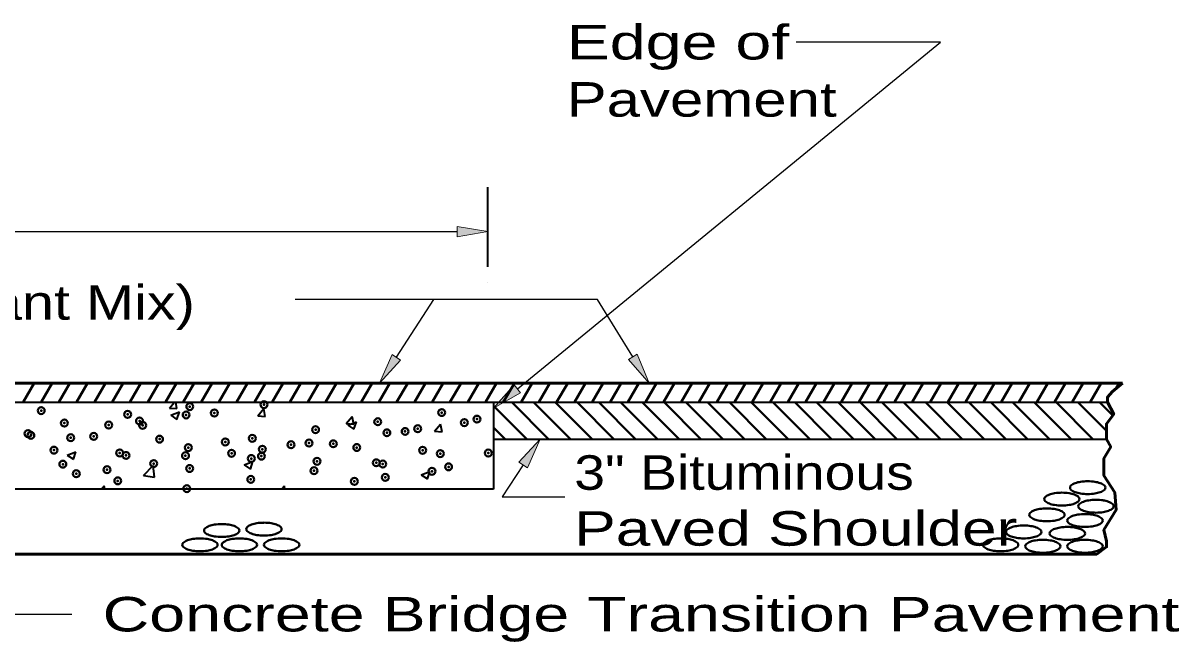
# Model space of a CAD drawing. Extents: x 36.4 to 71.7, y 0.5 to 22.5.
# Drawn here: x 57.119 to 61.81, y 3.21 to 5.719 of the extents above; entities that cross this region are included whole.
import ezdxf

# ---------------------------------------------------------------- set-up
doc = ezdxf.new("R2010")
doc.units = 0
doc.header["$LTSCALE"] = 0.056
doc.header["$PDMODE"] = 32
doc.header["$PDSIZE"] = 0.028
for name, color, linetype, lineweight in [('1', 7, 'Continuous', 40), ('3', 7, 'Continuous', 13), ('6', 7, 'Continuous', 13)]:
    doc.layers.add(name, color=color, linetype=linetype, lineweight=lineweight)

msp = doc.modelspace()

# ---------------------------------------------------------------- hatches: boundary and pattern name
at = {"layer": '1'}
msp.add_hatch(color=256, dxfattribs=at).paths.add_polyline_path([(58.88025, 4.85283), (58.88025, 4.8945), (59.00525, 4.87358), (59.00525, 4.87358)])
at = {"layer": '3'}
for points in [[(58.65083, 4.35233), (58.61592, 4.37517), (58.56508, 4.25908), (58.56508, 4.25908)], [(59.611, 4.37633), (59.57558, 4.35433), (59.65917, 4.25908), (59.65917, 4.25908)], [(59.13783, 4.22), (59.1115, 4.25225), (59.02792, 4.157), (59.02792, 4.157)], [(59.13108, 3.939), (59.16575, 3.916), (59.21733, 4.03183), (59.21733, 4.03183)]]:
    msp.add_hatch(color=256, dxfattribs=at).paths.add_polyline_path(points)

# ---------------------------------------------------------------- linework, layer by layer
at = {"layer": '1', "lineweight": 35}
for p, q in [((59.00525, 4.731), (59.00525, 5.05367)), ((55.79492, 4.1815), (59.02792, 4.1815)), ((57.71308, 4.15808), (57.73275, 4.1815)), ((57.743, 4.1555), (57.73825, 4.1815)), ((59.02792, 4.1815), (59.02792, 3.82925)), ((59.02792, 4.1815), (61.51975, 4.1815)), ((57.71308, 4.15808), (57.743, 4.1555)), ((57.71775, 4.12875), (57.75283, 4.14217)), ((57.71775, 4.12875), (57.74267, 4.11192)), ((57.74267, 4.11192), (57.75283, 4.14217)), ((58.07175, 4.12675), (58.09583, 4.1555)), ((58.10167, 4.12408), (58.09583, 4.15542)), ((58.07175, 4.12675), (58.10167, 4.12408)), ((58.43042, 4.09533), (58.4545, 4.12408)), ((58.43042, 4.09533), (58.46025, 4.09275)), ((58.43633, 4.08867), (58.47133, 4.10208)), ((58.43633, 4.08867), (58.46125, 4.07192)), ((58.46025, 4.09275), (58.4545, 4.12408)), ((58.46125, 4.07192), (58.47133, 4.10208)), ((58.789, 4.064), (58.81308, 4.09275)), ((58.81892, 4.06133), (58.81308, 4.09267)), ((58.789, 4.064), (58.81892, 4.06133)), ((59.02792, 4.03183), (61.5155, 4.03183)), ((57.29767, 3.96742), (57.33267, 3.98092)), ((57.29767, 3.96742), (57.32258, 3.95067)), ((57.32258, 3.95067), (57.33267, 3.98092)), ((58.01625, 3.92742), (58.05125, 3.94083)), ((58.04108, 3.91058), (58.05125, 3.94083)), ((57.60725, 3.88433), (57.64617, 3.92492)), ((57.65167, 3.87742), (57.64617, 3.92492)), ((58.01625, 3.92742), (58.04108, 3.91067)), ((58.73483, 3.88733), (58.76983, 3.90083)), ((58.75967, 3.87058), (58.76983, 3.90075)), ((57.60725, 3.88433), (57.65167, 3.87742)), ((58.73483, 3.88733), (58.75967, 3.87058)), ((59.02792, 3.82925), (55.79492, 3.82925)), ((57.43717, 3.82925), (57.448, 3.84208)), ((57.45033, 3.82925), (57.448, 3.84208)), ((58.16733, 3.82925), (58.17975, 3.84217)), ((58.18133, 3.82925), (58.17975, 3.84217))]:
    msp.add_line(p, q, dxfattribs=at)
at = {"layer": '1', "lineweight": 25}
msp.add_line((52.59792, 4.87367), (58.88025, 4.87367), dxfattribs=at)
at = {"layer": '1', "lineweight": 53}
msp.add_line((55.79492, 4.25908), (61.58058, 4.25908), dxfattribs=at)
at = {"layer": '1'}
for p, q in [((57.11908, 4.1815), (57.16383, 4.25908)), ((57.19125, 4.1815), (57.236, 4.25908)), ((57.26342, 4.1815), (57.30817, 4.25908)), ((57.33558, 4.1815), (57.38033, 4.25908)), ((57.40775, 4.1815), (57.4525, 4.25908)), ((57.47992, 4.1815), (57.52467, 4.25908)), ((57.55208, 4.1815), (57.59683, 4.25908)), ((57.62425, 4.1815), (57.669, 4.25908)), ((57.69642, 4.1815), (57.74117, 4.25908)), ((57.69642, 4.1815), (57.74117, 4.25908)), ((57.76858, 4.1815), (57.81342, 4.25908)), ((57.84075, 4.1815), (57.88558, 4.25908)), ((57.91292, 4.1815), (57.95775, 4.25908)), ((57.98508, 4.1815), (58.02992, 4.25908)), ((58.05725, 4.1815), (58.10208, 4.25908)), ((58.12942, 4.1815), (58.17425, 4.25908)), ((58.20158, 4.1815), (58.24642, 4.25908)), ((58.27375, 4.1815), (58.31858, 4.25908)), ((58.34592, 4.1815), (58.39075, 4.25908)), ((58.41808, 4.1815), (58.46292, 4.25908)), ((58.49025, 4.1815), (58.53508, 4.25908)), ((58.56242, 4.1815), (58.60725, 4.25908)), ((58.63458, 4.1815), (58.67942, 4.25908)), ((58.70675, 4.1815), (58.75158, 4.25908)), ((58.77892, 4.1815), (58.82375, 4.25908)), ((58.85108, 4.1815), (58.89592, 4.25908)), ((58.92325, 4.1815), (58.96808, 4.25908)), ((58.9955, 4.1815), (59.04025, 4.25908)), ((59.06767, 4.1815), (59.11242, 4.25908)), ((59.13983, 4.1815), (59.18458, 4.25908)), ((59.212, 4.1815), (59.25675, 4.25908)), ((59.28417, 4.1815), (59.32892, 4.25908)), ((59.35633, 4.1815), (59.40108, 4.25908)), ((59.4285, 4.1815), (59.47325, 4.25908)), ((59.50067, 4.1815), (59.54542, 4.25908)), ((59.57283, 4.1815), (59.61758, 4.25908)), ((59.645, 4.1815), (59.68975, 4.25908)), ((59.71717, 4.1815), (59.76192, 4.25908)), ((59.78933, 4.1815), (59.83408, 4.25908)), ((59.8615, 4.1815), (59.90625, 4.25908)), ((59.93367, 4.1815), (59.97842, 4.25908)), ((60.00583, 4.1815), (60.05058, 4.25908)), ((60.078, 4.1815), (60.12275, 4.25908)), ((60.15017, 4.1815), (60.19492, 4.25908)), ((60.22233, 4.1815), (60.26708, 4.25908)), ((60.2945, 4.1815), (60.33925, 4.25908)), ((60.36667, 4.1815), (60.41142, 4.25908)), ((60.43883, 4.1815), (60.48358, 4.25908)), ((60.511, 4.1815), (60.55575, 4.25908)), ((60.58317, 4.1815), (60.628, 4.25908)), ((60.65533, 4.1815), (60.70017, 4.25908)), ((60.7275, 4.1815), (60.77233, 4.25908)), ((60.79967, 4.1815), (60.8445, 4.25908)), ((60.87183, 4.1815), (60.91667, 4.25908)), ((60.944, 4.1815), (60.98883, 4.25908)), ((61.01617, 4.1815), (61.061, 4.25908)), ((61.08833, 4.1815), (61.13317, 4.25908)), ((61.1605, 4.1815), (61.20533, 4.25908)), ((61.23267, 4.1815), (61.2775, 4.25908)), ((61.30483, 4.1815), (61.34967, 4.25908)), ((61.377, 4.1815), (61.42183, 4.25908)), ((61.44917, 4.1815), (61.494, 4.25908)), ((61.55183, 4.23433), (61.56617, 4.25908)), ((59.25125, 4.03183), (59.10158, 4.1815)), ((59.33967, 4.03183), (59.18992, 4.1815)), ((59.428, 4.03183), (59.27833, 4.1815)), ((59.51642, 4.03183), (59.36675, 4.1815)), ((59.60483, 4.03183), (59.45508, 4.1815)), ((59.69317, 4.03183), (59.5435, 4.1815)), ((59.78158, 4.03183), (59.63183, 4.1815)), ((59.87, 4.03183), (59.72025, 4.1815)), ((59.95833, 4.03183), (59.80867, 4.1815)), ((60.04675, 4.03183), (59.897, 4.1815)), ((60.13517, 4.03183), (59.98542, 4.1815)), ((60.2235, 4.03183), (60.07383, 4.1815)), ((60.31192, 4.03183), (60.16217, 4.1815)), ((60.40033, 4.03183), (60.25058, 4.1815)), ((60.48867, 4.03183), (60.339, 4.1815)), ((60.57708, 4.03183), (60.42733, 4.1815)), ((60.6655, 4.03183), (60.51575, 4.1815)), ((60.75383, 4.03183), (60.60417, 4.1815)), ((60.84225, 4.03183), (60.6925, 4.1815)), ((60.93067, 4.03183), (60.78092, 4.1815)), ((61.019, 4.03183), (60.86933, 4.1815)), ((61.10742, 4.03183), (60.95767, 4.1815)), ((61.19583, 4.03183), (61.04608, 4.1815)), ((61.28417, 4.03183), (61.1345, 4.1815)), ((61.37258, 4.03183), (61.22283, 4.1815)), ((61.461, 4.03183), (61.31125, 4.1815)), ((61.5155, 4.06567), (61.39967, 4.1815)), ((61.54125, 4.12833), (61.488, 4.1815)), ((59.16283, 4.03183), (59.02792, 4.16675)), ((59.0745, 4.03183), (59.02792, 4.07842))]:
    msp.add_line(p, q, dxfattribs=at)
at = {"layer": '1', "lineweight": 13}
msp.add_lwpolyline([(58.88025, 4.85283), (58.88025, 4.8945), (59.00525, 4.87358), (59.00525, 4.87358)], close=True, dxfattribs=at)
at = {"layer": '1', "lineweight": 53}
for points in [[(61.58058, 4.25908), (61.54075, 4.22475), (61.51975, 4.20192), (61.51975, 4.1815)], [(61.51975, 4.1815), (61.545, 4.13333), (61.5155, 4.09358), (61.5155, 4.03183)], [(61.5155, 4.03183), (61.53308, 4.00033), (61.50542, 3.954), (61.50542, 3.88442), (61.54967, 3.81483), (61.55517, 3.74525), (61.50542, 3.66408), (61.5165, 3.61775), (61.5165, 3.5945), (61.47658, 3.56558)], [(55.79492, 3.82925), (55.79492, 3.56558), (61.47658, 3.56558)]]:
    msp.add_lwpolyline(points, dxfattribs=at)
at = {"layer": '1'}
for centre, radius, start, end in [((61.4075, 3.80233), 0.05453, 109.95668, 131.23889), ((61.42675, 3.749), 0.11118, 98.4919, 109.89511), ((61.44008, 3.66342), 0.19781, 90.09713, 98.65062), ((61.43933, 3.664), 0.19725, 81.33699, 89.89049), ((61.45267, 3.749), 0.11118, 70.10489, 81.5081), ((61.47192, 3.80233), 0.05453, 48.76111, 70.04332), ((61.3025, 3.75592), 0.05453, 109.95668, 131.23889), ((61.32217, 3.70267), 0.11128, 98.70124, 110.10445), ((61.3345, 3.61708), 0.19777, 89.93573, 98.48922), ((61.33492, 3.61767), 0.19721, 81.49885, 90.05234), ((61.34725, 3.70267), 0.11128, 69.89554, 81.29876), ((61.37883, 3.83508), 0.01094, 179.58205, 228.34293), ((61.37875, 3.83517), 0.01084, 131.44045, 180.20133), ((61.4075, 3.86792), 0.05453, 228.76111, 250.04332), ((61.36692, 3.75592), 0.05453, 48.76111, 70.04332), ((61.42675, 3.92125), 0.11118, 250.10489, 261.5081), ((61.44008, 4.00683), 0.19781, 261.34937, 269.90286), ((61.43933, 4.00625), 0.19725, 270.10951, 278.663), ((61.45267, 3.92125), 0.11118, 278.4919, 289.89511), ((61.47192, 3.86792), 0.05453, 289.95668, 311.23889), ((61.50067, 3.83508), 0.01089, 0.28337, 49.04425), ((61.50058, 3.83517), 0.01098, 311.1756, 359.93648), ((61.27375, 3.78867), 0.01089, 130.95574, 179.71662), ((61.27375, 3.78883), 0.01089, 180.28337, 229.04425), ((61.3025, 3.82158), 0.05453, 228.76111, 250.04332), ((61.32217, 3.87483), 0.11128, 249.89554, 261.29876), ((61.3345, 3.96042), 0.19777, 261.51077, 270.06427), ((61.33492, 3.95983), 0.19721, 269.94766, 278.50115), ((61.34725, 3.87483), 0.11128, 278.70124, 290.10445), ((61.36692, 3.82158), 0.05453, 289.95668, 311.23889), ((61.412, 3.75975), 0.01098, 131.1756, 179.93648), ((61.41192, 3.75983), 0.01089, 180.28337, 229.04425), ((61.39567, 3.78867), 0.01089, 0.28337, 49.04425), ((61.39567, 3.78883), 0.01089, 310.95574, 359.71662), ((61.44067, 3.727), 0.05453, 109.95668, 131.23889), ((61.45992, 3.67367), 0.11118, 98.4919, 109.89511), ((61.47267, 3.58808), 0.19777, 89.93573, 98.48922), ((61.47308, 3.58867), 0.19721, 81.49885, 90.05234), ((61.48583, 3.67367), 0.11118, 70.10489, 81.5081), ((61.50508, 3.727), 0.05453, 48.76111, 70.04332), ((61.53383, 3.75983), 0.01089, 310.95574, 359.71662), ((61.53375, 3.75975), 0.01098, 0.06351, 48.82439), ((61.21308, 3.725), 0.01098, 180.06351, 228.82439), ((61.213, 3.72492), 0.01089, 130.95574, 179.71662), ((61.24175, 3.69242), 0.05433, 110.0778, 131.36001), ((61.24175, 3.7575), 0.05433, 228.63999, 249.9222), ((61.261, 3.63842), 0.11159, 98.43909, 109.84231), ((61.261, 3.8115), 0.11159, 250.15769, 261.5609), ((61.27433, 3.55383), 0.19725, 90.10951, 98.663), ((61.27358, 3.55325), 0.19781, 81.34937, 89.90286), ((61.28692, 3.63883), 0.11118, 70.10489, 81.5081), ((61.28692, 3.81108), 0.11118, 278.4919, 289.89511), ((61.30617, 3.69217), 0.05453, 48.76111, 70.04332), ((61.30617, 3.75775), 0.05453, 289.95668, 311.23889), ((61.33492, 3.725), 0.01084, 359.79866, 48.55954), ((61.33483, 3.72492), 0.01094, 311.65707, 0.41795), ((61.36775, 3.70183), 0.01094, 131.65707, 180.41795), ((61.39642, 3.669), 0.05453, 109.95668, 131.23889), ((61.41575, 3.61525), 0.11159, 98.43909, 109.84231), ((61.42908, 3.53067), 0.19725, 90.10951, 98.663), ((61.44067, 3.79258), 0.05453, 228.76111, 250.04332), ((61.46033, 3.84583), 0.11128, 249.89554, 261.29876), ((61.42833, 3.53008), 0.19781, 81.34937, 89.90286), ((61.47267, 3.93142), 0.19777, 261.51077, 270.06427), ((61.44167, 3.61567), 0.11118, 70.10489, 81.5081), ((61.47308, 3.93083), 0.19721, 269.94766, 278.50115), ((61.46092, 3.669), 0.05453, 48.76111, 70.04332), ((61.48958, 3.70183), 0.01094, 359.58205, 48.34293), ((61.48542, 3.84583), 0.11128, 278.70124, 290.10445), ((61.50508, 3.79258), 0.05453, 289.95668, 311.23889), ((57.86383, 3.66125), 0.01094, 131.65707, 180.41795), ((57.86375, 3.66117), 0.01084, 179.79866, 228.55954), ((57.8925, 3.62842), 0.05453, 109.95668, 131.23889), ((57.91175, 3.57508), 0.11118, 98.4919, 109.89511), ((57.92508, 3.4895), 0.19781, 90.09713, 98.65062), ((57.92433, 3.49008), 0.19725, 81.33699, 89.89049), ((57.93767, 3.57467), 0.11159, 70.15769, 81.5609), ((57.95692, 3.62867), 0.05433, 48.63999, 69.9222), ((57.98567, 3.66125), 0.01089, 310.95574, 359.71662), ((57.98558, 3.66117), 0.01098, 0.06351, 48.82439), ((58.03508, 3.667), 0.01084, 131.44045, 180.20133), ((58.03508, 3.667), 0.01084, 179.79866, 228.55954), ((58.06383, 3.63417), 0.05453, 109.95668, 131.23889), ((58.0835, 3.58092), 0.11128, 98.70124, 110.10445), ((58.09583, 3.49533), 0.19777, 89.93573, 98.48922), ((58.09625, 3.49592), 0.19721, 81.49885, 90.05234), ((58.10858, 3.58092), 0.11128, 69.89554, 81.29876), ((58.12825, 3.63417), 0.05453, 48.76111, 70.04332), ((58.157, 3.66692), 0.01089, 0.28337, 49.04425), ((58.157, 3.66708), 0.01089, 310.95574, 359.71662), ((61.119, 3.65533), 0.01089, 130.95574, 179.71662), ((61.14775, 3.62258), 0.05453, 109.95668, 131.23889), ((61.16742, 3.56933), 0.11128, 98.70124, 110.10445), ((61.17975, 3.48375), 0.19777, 89.93573, 98.48922), ((61.18017, 3.48433), 0.19721, 81.49885, 90.05234), ((61.1925, 3.56933), 0.11128, 69.89554, 81.29876), ((61.21217, 3.62258), 0.05453, 48.76111, 70.04332), ((61.27375, 3.89608), 0.19721, 261.49885, 270.05234), ((61.24092, 3.65533), 0.01089, 0.28337, 49.04425), ((61.27417, 3.89667), 0.19777, 269.93573, 278.48922), ((61.32458, 3.61683), 0.05453, 109.95668, 131.23889), ((61.34383, 3.5635), 0.11118, 98.4919, 109.89511), ((61.35658, 3.47792), 0.19777, 89.93573, 98.48922), ((61.357, 3.4785), 0.19721, 81.49885, 90.05234), ((61.36767, 3.70175), 0.01084, 179.79866, 228.55954), ((61.39642, 3.73458), 0.05453, 228.76111, 250.04332), ((61.41575, 3.78833), 0.11159, 250.15769, 261.5609), ((61.36975, 3.56308), 0.11159, 70.15769, 81.5609), ((61.42908, 3.87292), 0.19725, 261.33699, 269.89049), ((61.389, 3.61708), 0.05433, 48.63999, 69.9222), ((61.42833, 3.8735), 0.19781, 270.09713, 278.65062), ((61.44167, 3.78792), 0.11118, 278.4919, 289.89511), ((61.46092, 3.73458), 0.05453, 289.95668, 311.23889), ((61.48967, 3.70175), 0.01084, 311.44045, 0.20133), ((57.80408, 3.57042), 0.05453, 109.95668, 131.23889), ((57.82333, 3.51708), 0.11118, 98.4919, 109.89511), ((57.83667, 3.4315), 0.19781, 90.09713, 98.65062), ((57.83592, 3.43208), 0.19725, 81.33699, 89.89049), ((57.8925, 3.694), 0.05453, 228.76111, 250.04332), ((57.84925, 3.51708), 0.11118, 70.10489, 81.5081), ((57.91175, 3.74733), 0.11118, 250.10489, 261.5081), ((57.8685, 3.57042), 0.05453, 48.76111, 70.04332), ((57.92508, 3.83292), 0.19781, 261.34937, 269.90286), ((57.92433, 3.83233), 0.19725, 270.10951, 278.663), ((57.96442, 3.57067), 0.05433, 110.0778, 131.36001), ((57.98367, 3.51667), 0.11159, 98.43909, 109.84231), ((57.93767, 3.74775), 0.11159, 278.43909, 289.84231), ((57.997, 3.43208), 0.19725, 90.10951, 98.663), ((57.95692, 3.69375), 0.05433, 290.0778, 311.36001), ((57.99625, 3.4315), 0.19781, 81.34937, 89.90286), ((58.00958, 3.51708), 0.11118, 70.10489, 81.5081), ((58.06383, 3.69983), 0.05453, 228.76111, 250.04332), ((58.0835, 3.75308), 0.11128, 249.89554, 261.29876), ((58.02883, 3.57042), 0.05453, 48.76111, 70.04332), ((58.09583, 3.83867), 0.19777, 261.51077, 270.06427), ((58.09625, 3.83808), 0.19721, 269.94766, 278.50115), ((58.13567, 3.57042), 0.05453, 109.95668, 131.23889), ((58.155, 3.51667), 0.11159, 98.43909, 109.84231), ((58.10858, 3.75308), 0.11128, 278.70124, 290.10445), ((58.16833, 3.43208), 0.19725, 90.10951, 98.663), ((58.12825, 3.69983), 0.05453, 289.95668, 311.23889), ((58.1675, 3.43208), 0.19725, 81.33699, 89.89049), ((58.18083, 3.51667), 0.11159, 70.15769, 81.5609), ((58.20017, 3.57042), 0.05453, 48.76111, 70.04332), ((61.05383, 3.57042), 0.05453, 109.95668, 131.23889), ((61.07308, 3.51708), 0.11118, 98.4919, 109.89511), ((61.08642, 3.43208), 0.19725, 90.10951, 98.663), ((61.08567, 3.4315), 0.19781, 81.34937, 89.90286), ((61.11908, 3.65542), 0.01098, 180.06351, 228.82439), ((61.14758, 3.68825), 0.05441, 228.96563, 250.24784), ((61.099, 3.51708), 0.11118, 70.10489, 81.5081), ((61.16742, 3.7415), 0.11128, 249.89554, 261.29876), ((61.11825, 3.57042), 0.05453, 48.76111, 70.04332), ((61.17975, 3.82708), 0.19777, 261.51077, 270.06427), ((61.18017, 3.8265), 0.19721, 269.94766, 278.50115), ((61.22517, 3.56492), 0.05433, 110.0778, 131.36001), ((61.24442, 3.51092), 0.11159, 98.43909, 109.84231), ((61.1925, 3.7415), 0.11128, 278.70124, 290.10445), ((61.25717, 3.42633), 0.19721, 89.94766, 98.50115), ((61.21233, 3.68825), 0.05441, 289.75216, 311.03436), ((61.24083, 3.65542), 0.01098, 311.1756, 359.93648), ((61.25758, 3.42575), 0.19777, 81.51077, 90.06427), ((61.29592, 3.64967), 0.01094, 131.65707, 180.41795), ((61.29583, 3.64958), 0.01084, 179.79866, 228.55954), ((61.27033, 3.51133), 0.11118, 70.10489, 81.5081), ((61.32458, 3.68242), 0.05453, 228.76111, 250.04332), ((61.34383, 3.73575), 0.11118, 250.10489, 261.5081), ((61.28958, 3.56467), 0.05453, 48.76111, 70.04332), ((61.35717, 3.82133), 0.19781, 261.34937, 269.90286), ((61.35642, 3.82075), 0.19725, 270.10951, 278.663), ((61.39642, 3.56467), 0.05453, 109.95668, 131.23889), ((61.41575, 3.51092), 0.11159, 98.43909, 109.84231), ((61.36975, 3.73617), 0.11159, 278.43909, 289.84231), ((61.4285, 3.42633), 0.19721, 89.94766, 98.50115), ((61.389, 3.68217), 0.05433, 290.0778, 311.36001), ((61.41775, 3.64967), 0.01089, 310.95574, 359.71662), ((61.41767, 3.64958), 0.01098, 0.06351, 48.82439), ((61.42892, 3.42575), 0.19777, 81.51077, 90.06427), ((61.44167, 3.51133), 0.11118, 70.10489, 81.5081), ((61.46092, 3.56467), 0.05453, 48.76111, 70.04332), ((57.77542, 3.60317), 0.01094, 179.58205, 228.34293), ((57.77533, 3.60325), 0.01084, 131.44045, 180.20133), ((57.80408, 3.636), 0.05453, 228.76111, 250.04332), ((57.82333, 3.68933), 0.11118, 250.10489, 261.5081), ((57.83608, 3.77492), 0.19777, 261.51077, 270.06427), ((57.8365, 3.77433), 0.19721, 269.94766, 278.50115), ((57.84925, 3.68933), 0.11118, 278.4919, 289.89511), ((57.8685, 3.636), 0.05453, 289.95668, 311.23889), ((57.89725, 3.60317), 0.01089, 0.28337, 49.04425), ((57.89717, 3.60325), 0.01098, 311.1756, 359.93648), ((57.93575, 3.60325), 0.01098, 180.06351, 228.82439), ((57.93567, 3.60317), 0.01089, 130.95574, 179.71662), ((57.96442, 3.63575), 0.05433, 228.63999, 249.9222), ((57.98367, 3.68975), 0.11159, 250.15769, 261.5609), ((57.99642, 3.77433), 0.19721, 261.49885, 270.05234), ((57.99683, 3.77492), 0.19777, 269.93573, 278.48922), ((58.00958, 3.68933), 0.11118, 278.4919, 289.89511), ((58.02883, 3.636), 0.05453, 289.95668, 311.23889), ((58.05758, 3.60325), 0.01084, 359.79866, 48.55954), ((58.0575, 3.60317), 0.01094, 311.65707, 0.41795), ((58.107, 3.60317), 0.01094, 179.58205, 228.34293), ((58.10692, 3.60325), 0.01084, 131.44045, 180.20133), ((58.13567, 3.636), 0.05453, 228.76111, 250.04332), ((58.155, 3.68975), 0.11159, 250.15769, 261.5609), ((58.16775, 3.77433), 0.19721, 261.49885, 270.05234), ((58.16808, 3.77433), 0.19721, 269.94766, 278.50115), ((58.18083, 3.68975), 0.11159, 278.43909, 289.84231), ((58.20017, 3.636), 0.05453, 289.95668, 311.23889), ((58.22892, 3.60325), 0.01084, 359.79866, 48.55954), ((58.22883, 3.60317), 0.01094, 311.65707, 0.41795), ((61.02517, 3.60325), 0.01098, 180.06351, 228.82439), ((61.02508, 3.60317), 0.01089, 130.95574, 179.71662), ((61.05383, 3.636), 0.05453, 228.76111, 250.04332), ((61.07308, 3.68933), 0.11118, 250.10489, 261.5081), ((61.08583, 3.77433), 0.19721, 261.49885, 270.05234), ((61.08625, 3.77492), 0.19777, 269.93573, 278.48922), ((61.099, 3.68933), 0.11118, 278.4919, 289.89511), ((61.11825, 3.636), 0.05453, 289.95668, 311.23889), ((61.147, 3.60325), 0.01084, 359.79866, 48.55954), ((61.14692, 3.60317), 0.01094, 311.65707, 0.41795), ((61.1965, 3.59742), 0.01098, 131.1756, 179.93648), ((61.19642, 3.5975), 0.01089, 180.28337, 229.04425), ((61.22517, 3.63), 0.05433, 228.63999, 249.9222), ((61.24483, 3.68392), 0.11169, 249.94906, 261.35227), ((61.25717, 3.7685), 0.19721, 261.49885, 270.05234), ((61.25758, 3.76908), 0.19777, 269.93573, 278.48922), ((61.26992, 3.6835), 0.11128, 278.70124, 290.10445), ((61.28958, 3.63025), 0.05453, 289.95668, 311.23889), ((61.31833, 3.59742), 0.01084, 311.44045, 0.20133), ((61.31825, 3.5975), 0.01094, 359.58205, 48.34293), ((61.36775, 3.5975), 0.01094, 131.65707, 180.41795), ((61.36767, 3.59742), 0.01084, 179.79866, 228.55954), ((61.39642, 3.63025), 0.05453, 228.76111, 250.04332), ((61.41617, 3.68392), 0.11169, 249.94906, 261.35227), ((61.4285, 3.7685), 0.19721, 261.49885, 270.05234), ((61.42892, 3.76908), 0.19777, 269.93573, 278.48922), ((61.44125, 3.6835), 0.11128, 278.70124, 290.10445), ((61.46092, 3.63025), 0.05453, 289.95668, 311.23889), ((61.48958, 3.5975), 0.01094, 359.58205, 48.34293), ((61.48967, 3.59742), 0.01084, 311.44045, 0.20133)]:
    msp.add_arc(centre, radius, start, end, dxfattribs=at)
for p in [(57.79517, 4.164), (58.09617, 4.17175), (57.192, 4.1475), (57.54258, 4.132), (57.78033, 4.13017), (57.895, 4.13783), (58.81775, 4.13975), (57.28592, 4.09683), (57.46583, 4.08875), (57.591, 4.10525), (57.60342, 4.08783), (58.3055, 4.07025), (58.55808, 4.10225), (58.72008, 4.074), (58.90942, 4.09892), (58.96075, 4.113), (57.13842, 4.05433), (57.15008, 4.04717), (57.31183, 4.03775), (57.40533, 4.043), (57.67225, 4.03175), (57.93917, 4.0205), (58.04875, 4.03508), (58.59492, 4.0575), (58.66917, 4.063), (57.24383, 3.98717), (57.51075, 3.97583), (57.78908, 3.99758), (57.96458, 3.9745), (58.08975, 3.991), (58.20608, 4.00917), (58.27917, 4.01592), (58.37758, 4.01292), (58.473, 3.99792), (58.73992, 3.98667), (59.00683, 3.97533), (57.27983, 3.93033), (57.5365, 3.96558), (57.64883, 3.93292), (57.77767, 3.96458), (58.04458, 3.95333), (58.086, 3.96283), (58.3115, 3.942), (58.552, 3.93583), (58.57842, 3.93075), (58.81167, 3.97333), (57.33425, 3.8915), (57.45942, 3.908), (57.79442, 3.91283), (58.29942, 3.90383), (58.77792, 3.90167), (58.84533, 3.9195), (57.50283, 3.86275), (58.04267, 3.86858), (58.46333, 3.86033), (58.58858, 3.87675), (57.783, 3.83117)]:
    msp.add_point(p, dxfattribs=at)
at = {"layer": '3', "lineweight": 25}
msp.add_line((58.63342, 4.36375), (58.78608, 4.59767), dxfattribs=at)
for points in [[(59.12467, 4.23608), (60.84225, 5.64142), (60.25642, 5.64142)], [(59.59333, 4.36533), (59.44925, 4.59767), (58.22242, 4.59767)], [(56.68642, 3.90042), (57.05092, 3.322), (57.31617, 3.322)], [(59.1485, 3.9275), (59.06258, 3.79742), (59.31683, 3.79742)]]:
    msp.add_lwpolyline(points, dxfattribs=at)
at = {"layer": '3'}
for points in [[(58.65083, 4.35233), (58.61592, 4.37517), (58.56508, 4.25908), (58.56508, 4.25908)], [(59.611, 4.37633), (59.57558, 4.35433), (59.65917, 4.25908), (59.65917, 4.25908)], [(59.13783, 4.22), (59.1115, 4.25225), (59.02792, 4.157), (59.02792, 4.157)], [(59.13108, 3.939), (59.16575, 3.916), (59.21733, 4.03183), (59.21733, 4.03183)]]:
    msp.add_lwpolyline(points, close=True, dxfattribs=at)
at = {"layer": '6'}
for p, q in [((59.00525, 4.87367), (59.00533, 4.87367)), ((59.00525, 4.6685), (59.00533, 4.6685))]:
    msp.add_line(p, q, dxfattribs=at)

# ---------------------------------------------------------------- texts
at = {"layer": '3'}
for s, width, p in [('Edge of', 1.4, (59.32467, 5.57133)), ('Pavement', 1.3, (59.32467, 5.3395)), ('2" Bituminous Overlay (Skid Resistant Mix)', 1.25, (53.36308, 4.51608)), ('3" Bituminous', 1.2, (59.3555, 3.82642)), ('Paved Shoulder', 1.35, (59.3555, 3.59975)), ('Concrete Bridge Transition Pavement', 1.4, (57.44117, 3.252))]:
    msp.add_text(s, height=0.14, dxfattribs=dict(at, width=width)).set_placement(p)

doc.saveas('drawing.dxf')
